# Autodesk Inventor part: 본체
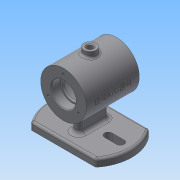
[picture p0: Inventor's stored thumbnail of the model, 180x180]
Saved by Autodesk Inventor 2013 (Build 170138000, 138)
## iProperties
Created: 2017-12
Part Number: 본체
Material: 일반
Document SubType Name: Modeling
Designer: Administrator
Density: 1 g/cm^3
Author: Administrator
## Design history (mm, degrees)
sketch "스케치1"
  geometry: C1 r 30 at (0, 0); 1 further point
  constraints: 1 centre point, 1 coincident
  dimensions: "d0" = 60 diameter of C1
extrude "돌출1" new body sketch "스케치1" stored distance "d2" = 70; taper "d3" = 0 deg
hole "구멍1" diameter "d6" = 28; stored, may be unused: countersink angle "d10" = 90 deg, drill point angle "d12" = 118 deg; dims "d4" = 10, "d5" = 10, "d7" = 6, "d8" = 32, "d9" = 12, "d11" = 8
hole "구멍2" diameter "d15" = 32; stored, may be unused: countersink angle "d19" = 90 deg, drill point angle "d21" = 0 deg; dims "d13" = 10, "d14" = 10, "d16" = 6, "d17" = 32, "d18" = 12, "d20" = 12
node "작업 평면1"
sketch "스케치2"
  geometry: L1 (-42.426, -35)-(42.426, -35); L2 (-42.426, 35)-(42.426, 35); A1 r 55 centre (0, 0) between (42.426, -35) and (42.426, 35); A2 r 55 centre (0, 0) between (-42.426, 35) and (-42.426, -35); 1 further point
  constraints: 4 end point, 4 point on circle, 2 centre point, 1 coincident, 1 horizontal, 1 parallel
  dimensions: "d24" = 35 distance from line of L1 A1.centre; "d25" = 35 distance from line of L2 point (0, 0); "d26" = 55 radius of A2; "d27" = 55 radius of A1
extrude "돌출2" join sketch "스케치2" distance "d28" = 10; taper "d29" = 0 deg
sketch "스케치3"
  geometry: L1 (0, -20)-(0, -20); L2 (5, -15)-(5, 15); L3 (0, 20)-(0, 20); L4 (-5, 15)-(-5, -15); A1 r 55 centre (0, 0) between (42.426, -35) and (42.426, 35) reference; A2 r 5 centre (0, -15) between (-5, -15) and (0, -20); A3 r 5 centre (0, -15) between (0, -20) and (5, -15); A4 r 5 centre (0, 15) between (0, 20) and (-5, 15); A5 r 5 centre (0, 15) between (5, 15) and (0, 20); 5 further points
  constraints: 8 end point, 8 point on circle, 8 tangent, 6 point on line, 4 centre point, 3 equal radius, 2 midpoint, 2 parallel, 1 horizontal, 1 horizontal alignment, 1 perpendicular, 1 vertical alignment
  dimensions: "d30" = 10 distance of point (5, 20) point (-5, 20); "d32" = 40 distance of point (-5, 20) point (-5, -20); "d33" = 5 radius of A2
extrude "돌출3" join sketch "스케치3" stored distance "d34" = 10; taper "d35" = 0 deg
sketch "스케치4"
  geometry: L1 (-20, 25)-(20, 25); L2 (20, 25)-(20, 0); L3 (20, 0)-(-20, 0); L4 (-20, 0)-(-20, 25); 2 further points
  constraints: 8 end point, 2 coincident, 2 parallel, 1 horizontal, 1 midpoint, 1 perpendicular
  dimensions: "d36" = 25 distance of L1.end L2.end; "d38" = 40 distance of L1.start L1.end
revolve "회전1" sketch "스케치4" stored, may be unused: angle "d39" = 90 deg
node "작업 평면2"
sketch "스케치5"
  geometry: C1 r 8 at (0, 0); 1 further point
  constraints: 1 centre point, 1 coincident
  dimensions: "d41" = 16 diameter of C1
extrude "돌출4" join sketch "스케치5" stored distance "d42" = 10; taper "d43" = 0 deg
hole "구멍3" diameter "d46" = 8; stored, may be unused: countersink angle "d50" = 90 deg, drill point angle "d52" = 0 deg; dims "d44" = 10, "d45" = 10, "d47" = 6, "d48" = 32, "d49" = 12, "d51" = 25
sketch "스케치6"
  geometry: L1 (-40, -5)-(-24, -5); L2 (-19, 0)-(-19, 0); L3 (-24, 5)-(-40, 5); L4 (-45, 0)-(-45, 0); A1 r 55 centre (0, 0) between (42.426, -35) and (42.426, 35) reference; A2 r 5 centre (-40, 0) between (-45, 0) and (-40, -5); A3 r 5 centre (-40, 0) between (-40, 5) and (-45, 0); A4 r 5 centre (-24, 0) between (-19, 0) and (-24, 5); A5 r 5 centre (-24, 0) between (-24, -5) and (-19, 0); 4 further points
  constraints: 8 end point, 8 point on circle, 8 tangent, 6 point on line, 4 centre point, 3 equal radius, 2 parallel, 1 horizontal, 1 horizontal alignment, 1 midpoint, 1 perpendicular
  dimensions: "d53" = 19 distance from line of L2 A1.centre; "d54" = 26 distance of point (-19, 5) point (-45, 5); "d55" = 10 distance of point (-45, 5) point (-45, -5); "d56" = 5 radius of A2
extrude "돌출5" cut sketch "스케치6" stored distance "d57" = 10; taper "d58" = 0 deg
sketch "스케치7"
  geometry: C1 r 16 at (0, 0) reference; 1 further point
  constraints: 1 vertical alignment
  dimensions: "d59" = 23 distance of point (0, 23) C1.centre
hole "구멍4" sketch "스케치7" at (0, 23) diameter "d60" = 3.242; stored, may be unused: countersink angle "d64" = 90 deg, drill point angle "d66" = 118 deg; dims "d61" = 8, "d62" = 32, "d63" = 12, "d65" = 10
fillet "모깎기1" dims "d70" = 5
fillet "모깎기2" dims "d71" = 3
fillet "모깎기3" dims "d72" = 3
fillet "모깎기4" dims "d73" = 3
fillet "모깎기5" dims "d74" = 0.3
fillet "모깎기6" dims "d75" = 3
chamfer "모따기1" distance "d76" = 1; stored, may be unused: second distance "d77" = 2, angle "d78" = 45 deg
node "작업 평면3"
sketch "스케치8"
  geometry: L1 (-35, 30)-(35, 30) reference; L2 (-35, 30)-(-35, -30) reference; 2 further points
  constraints: 1 other
  dimensions: "d80" = 30 distance from line of L1 point (0, 0); "d81" = 35 distance from line of L2 point (0, 0)
feature "엠보싱1" sketch "스케치8" dims "d82" = 0.5, "d83" = 0
node "솔리드1"
mirror "대칭1"
pattern_circular "원형 패턴1" dims angle "d68" = 360 deg
mirror "대칭2"
other parameters: "d22" = -62, "d40" = 37
